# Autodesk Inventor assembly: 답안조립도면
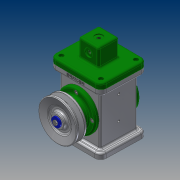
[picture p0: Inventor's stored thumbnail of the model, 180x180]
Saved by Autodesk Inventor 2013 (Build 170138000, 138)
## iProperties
Created: 2017-08
Part Number: 답안조립도면
Document SubType Name: Assembly
Designer: Windows7
Author: Windows7
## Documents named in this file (18)
- C:\Users\Windows7\Desktop\470808V1022\답안조립도면.iam
- C:\Users\Windows7\Desktop\470808V1022\본체.ipt
- C:\Users\Windows7\Desktop\470808V1022\덮개.ipt
- C:\Users\Windows7\Desktop\470808V1022\앞커버.ipt
- C:\Users\Windows7\Desktop\470808V1022\뒤커버.ipt
- C:\Users\Windows7\Desktop\470808V1022\편심축.ipt
- C:\Users\Windows7\Desktop\470808V1022\베어링 17 x 40 x 12.ipt
- C:\Users\Windows7\Desktop\470808V1022\링크.ipt
- C:\Users\Windows7\Desktop\470808V1022\슬라이더.ipt
- C:\Users\Windows7\Desktop\470808V1022\클레비스 핀 6 x 22.ipt
- 클레비스 핀 6 x 22.ipt
- C:\Users\Windows7\Desktop\470808V1022\E-링.ipt
- C:\Users\Windows7\Desktop\470808V1022\오일 실 17 30 8.ipt
- C:\Users\Windows7\Desktop\470808V1022\키 4 x 4 x 12.ipt
- C:\Users\Windows7\Desktop\470808V1022\V-벨트풀리.ipt
- C:\Users\Windows7\Desktop\470808V1022\와셔 4x16.ipt
- C:\Users\Windows7\Desktop\470808V1022\볼트 M4 x 8.ipt
- C:\Users\Windows7\Desktop\470808V1022\볼트 M4 x 10.ipt
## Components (2 placed, 2 different names)
1. E-링:1
2. V-벨트풀리:1
